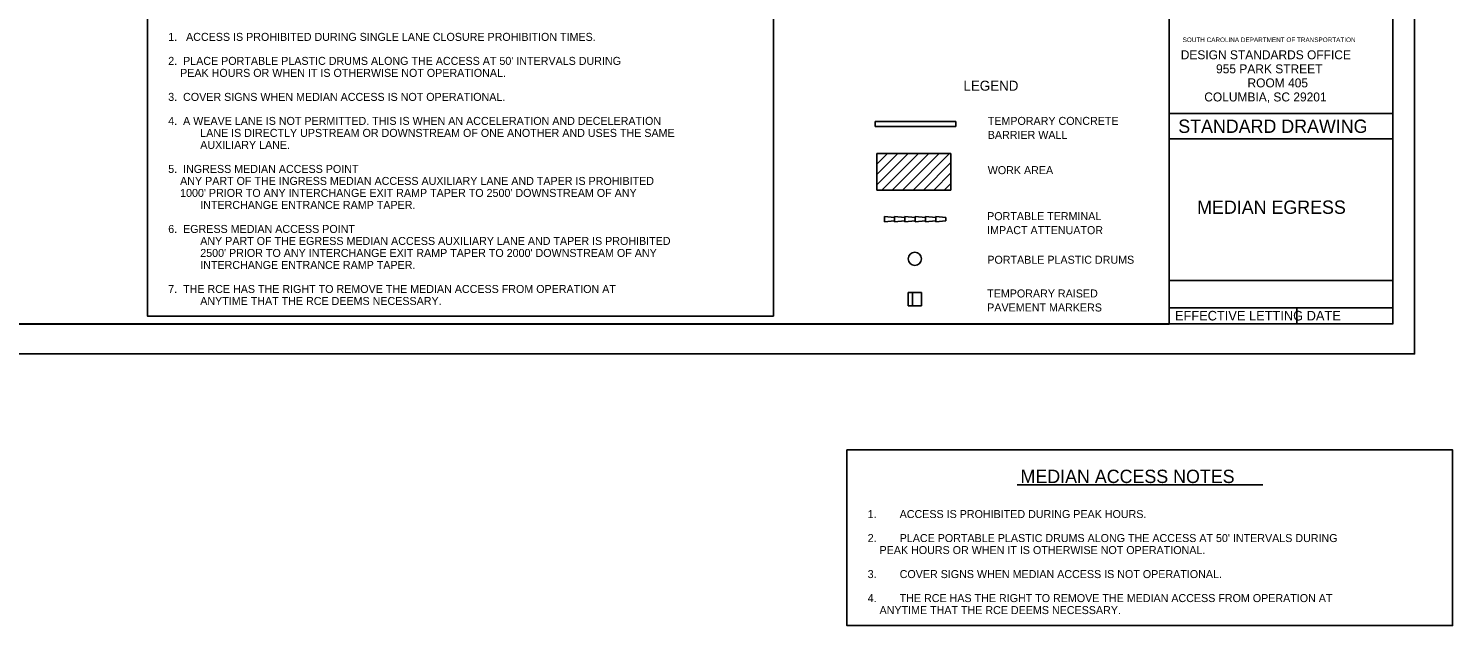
# Model space of a CAD drawing. Extents: x -2433 to -1135, y -5611 to -4633.
# Drawn here: x -1989 to -1135, y -5611 to -5253 of the extents above; entities that cross this region are included whole.
import ezdxf

# ---------------------------------------------------------------- set-up
doc = ezdxf.new("R2010")
doc.units = 0
for name, color, linetype in [('Level 42', 7, 'Continuous'), ('Level 45', 7, 'Continuous'), ('Level 47', 7, 'Continuous'), ('Level 48', 7, 'Continuous'), ('Level 50', 7, 'Continuous'), ('TR_WZ_TC_Edge Lines', 7, 'Continuous'), ('TR_WZ_TC_Text and Notes', 7, 'Continuous')]:
    doc.layers.add(name, color=color, linetype=linetype)

msp = doc.modelspace()

# ---------------------------------------------------------------- linework, layer by layer
at = {"layer": 'Level 42'}
for p, q in [((-1304.73, -5430.02), (-1304.73, -4648.85)), ((-1170.57, -5430.02), (-1170.57, -4648.81)), ((-1304.73, -5303.75), (-1170.64, -5303.75)), ((-1304.73, -5318.83), (-1170.64, -5318.83)), ((-1304.73, -5403.82), (-1170.64, -5403.82)), ((-1304.73, -5420.2), (-1170.72, -5420.2)), ((-1228.17, -5420.2), (-1228.17, -5429.79)), ((-1170.64, -5429.98), (-2364.77, -5429.98))]:
    msp.add_line(p, q, dxfattribs=at)
msp.add_lwpolyline([(-2364.77, -4648.78), (-1304.73, -4648.78), (-1304.73, -5430.02), (-2364.77, -5430.02)], close=True, dxfattribs=at)
at = {"layer": 'Level 45'}
for p, q in [((-1461.35, -5419.02), (-1461.35, -5411.1)), ((-1461.35, -5411.1), (-1458.71, -5411.1)), ((-1453.43, -5411.1), (-1458.71, -5411.1)), ((-1458.71, -5411.1), (-1458.71, -5419.02)), ((-1453.43, -5419.02), (-1453.43, -5411.1)), ((-1461.35, -5419.02), (-1458.71, -5419.02)), ((-1458.71, -5419.02), (-1453.43, -5419.02))]:
    msp.add_line(p, q, dxfattribs=at)
at = {"layer": 'Level 47'}
for p, q in [((-1480.11, -5349.74), (-1480.11, -5327.82)), ((-1480.11, -5346.49), (-1461.44, -5327.82)), ((-1480.11, -5340.26), (-1467.66, -5327.82)), ((-1480.11, -5334.04), (-1473.88, -5327.82)), ((-1480.11, -5327.82), (-1435.7, -5327.82)), ((-1477.14, -5349.74), (-1455.22, -5327.82)), ((-1470.92, -5349.74), (-1448.99, -5327.82)), ((-1464.7, -5349.74), (-1442.77, -5327.82)), ((-1458.48, -5349.74), (-1436.55, -5327.82)), ((-1435.7, -5349.74), (-1435.7, -5327.82)), ((-1452.25, -5349.74), (-1435.7, -5333.19)), ((-1446.03, -5349.74), (-1435.7, -5339.41)), ((-1439.81, -5349.74), (-1435.7, -5345.63)), ((-1480.11, -5349.74), (-1435.7, -5349.74))]:
    msp.add_line(p, q, dxfattribs=at)
at = {"layer": 'Level 48'}
for p, q in [((-1432.83, -5308.63), (-1481.16, -5308.63)), ((-1481.16, -5308.63), (-1481.16, -5311.56)), ((-1481.16, -5311.56), (-1432.83, -5311.56))]:
    msp.add_line(p, q, dxfattribs=at)
msp.add_lwpolyline([(-1432.83, -5311.56), (-1432.83, -5308.63)], dxfattribs=at)
at = {"layer": 'Level 50'}
for p, q in [((-1469.49, -5366.06), (-1475.64, -5365.54)), ((-1475.64, -5365.54), (-1475.64, -5368.7)), ((-1475.64, -5368.7), (-1469.49, -5368.18)), ((-1463.34, -5366.06), (-1469.49, -5365.53)), ((-1469.49, -5365.53), (-1469.49, -5368.7)), ((-1469.49, -5368.18), (-1469.49, -5366.06)), ((-1469.49, -5368.7), (-1463.34, -5368.18)), ((-1457.18, -5366.06), (-1463.34, -5365.54)), ((-1463.34, -5365.54), (-1463.34, -5368.7)), ((-1463.34, -5368.18), (-1463.34, -5366.06)), ((-1463.34, -5368.7), (-1457.18, -5368.18)), ((-1451.03, -5366.06), (-1457.18, -5365.54)), ((-1457.18, -5365.54), (-1457.18, -5368.7)), ((-1457.18, -5368.18), (-1457.18, -5366.06)), ((-1457.18, -5368.7), (-1451.03, -5368.18)), ((-1444.87, -5366.06), (-1451.03, -5365.54)), ((-1451.03, -5365.54), (-1451.03, -5368.7)), ((-1451.03, -5368.18), (-1451.03, -5366.06)), ((-1451.03, -5367.12), (-1451.03, -5367.12)), ((-1451.03, -5368.7), (-1444.88, -5368.18)), ((-1444.88, -5368.18), (-1444.87, -5366.06)), ((-1438.72, -5366.06), (-1444.87, -5365.54)), ((-1444.87, -5365.54), (-1444.87, -5368.7)), ((-1444.87, -5368.7), (-1438.72, -5368.18)), ((-1438.72, -5368.18), (-1438.72, -5366.06))]:
    msp.add_line(p, q, dxfattribs=at)
msp.add_lwpolyline([(-2432.94, -4632.82), (-1157.59, -4632.82), (-1157.59, -5447.91), (-2432.94, -5447.91)], close=True, dxfattribs=at)
msp.add_circle((-1457.35, -5390.92), 3.96, dxfattribs=at)
at = {"layer": 'TR_WZ_TC_Edge Lines'}
for points in [[(-1917.72, -5229.67), (-1542.19, -5229.67), (-1542.19, -5425.27), (-1917.72, -5425.27)], [(-1498.14, -5505.54), (-1134.84, -5505.54), (-1134.84, -5610.83), (-1498.14, -5610.83)]]:
    msp.add_lwpolyline(points, close=True, dxfattribs=at)
at = {"layer": 'TR_WZ_TC_Text and Notes'}
msp.add_line((-1395.94, -5526.38), (-1248.62, -5526.38), dxfattribs=at)

# ---------------------------------------------------------------- texts
at = {"layer": 'Level 42'}
for s, height, p in [('SOUTH CAROLINA DEPARTMENT OF TRANSPORTATION', 2.76, (-1296.74, -5260.91)), ('DESIGN STANDARDS OFFICE', 5.3667, (-1297.86, -5271.2)), ('955 PARK STREET', 5.3667, (-1276.68, -5279.64)), ('LEGEND', 6, (-1428.24, -5290.07)), ('ROOM 405', 5.367, (-1257.82, -5288.07)), ('COLUMBIA, SC 29201', 5.3667, (-1283.76, -5296.5)), ('TEMPORARY CONCRETE', 4.8, (-1413.64, -5310.57)), ('STANDARD DRAWING', 8, (-1299.36, -5315.37)), ('BARRIER WALL', 4.8, (-1413.64, -5318.97)), ('WORK AREA', 4.8, (-1413.65, -5340.11)), ('MEDIAN EGRESS', 8, (-1288.02, -5363.92)), ('PORTABLE TERMINAL', 4.8, (-1414.02, -5367.7)), ('IMPACT ATTENUATOR', 4.8, (-1414.02, -5376.1)), ('PORTABLE PLASTIC DRUMS', 4.8, (-1413.9, -5393.85)), ('TEMPORARY RAISED', 4.8, (-1413.98, -5414.08)), ('PAVEMENT MARKERS', 4.8, (-1413.98, -5422.48)), ('EFFECTIVE LETTING DATE', 5.75, (-1301.36, -5427.87))]:
    msp.add_text(s, height=height, dxfattribs=at).set_placement(p)
at = {"layer": 'TR_WZ_TC_Text and Notes'}
for s, height, p in [('1.   ACCESS IS PROHIBITED DURING SINGLE LANE CLOSURE PROHIBITION TIMES.', 4.8, (-1905.26, -5260.18)), ("2.  PLACE PORTABLE PLASTIC DRUMS ALONG THE ACCESS AT 50' INTERVALS DURING", 4.8, (-1905.26, -5274.58)), ('    PEAK HOURS OR WHEN IT IS OTHERWISE NOT OPERATIONAL.', 4.8, (-1905.26, -5281.78)), ('3.  COVER SIGNS WHEN MEDIAN ACCESS IS NOT OPERATIONAL.', 4.8, (-1905.26, -5296.18)), ('4.  A WEAVE LANE IS NOT PERMITTED. THIS IS WHEN AN ACCELERATION AND DECELERATION ', 4.8, (-1905.26, -5310.58)), ('LANE IS DIRECTLY UPSTREAM OR DOWNSTREAM OF ONE ANOTHER AND USES THE SAME ', 4.8, (-1886.06, -5317.78)), ('AUXILIARY LANE.', 4.8, (-1886.06, -5324.98)), ('5.  INGRESS MEDIAN ACCESS POINT   ', 4.8, (-1905.26, -5339.38)), ('    ANY PART OF THE INGRESS MEDIAN ACCESS AUXILIARY LANE AND TAPER IS PROHIBITED ', 4.8, (-1905.26, -5346.58)), ("    1000' PRIOR TO ANY INTERCHANGE EXIT RAMP TAPER TO 2500' DOWNSTREAM OF ANY ", 4.8, (-1905.26, -5353.78)), ('INTERCHANGE ENTRANCE RAMP TAPER.', 4.8, (-1886.06, -5360.98)), ('6.  EGRESS MEDIAN ACCESS POINT', 4.8, (-1905.26, -5375.38)), ('ANY PART OF THE EGRESS MEDIAN ACCESS AUXILIARY LANE AND TAPER IS PROHIBITED ', 4.8, (-1886.06, -5382.58)), ("2500' PRIOR TO ANY INTERCHANGE EXIT RAMP TAPER TO 2000' DOWNSTREAM OF ANY ", 4.8, (-1886.06, -5389.78)), ('INTERCHANGE ENTRANCE RAMP TAPER.', 4.8, (-1886.06, -5396.98)), ('7.  THE RCE HAS THE RIGHT TO REMOVE THE MEDIAN ACCESS FROM OPERATION AT ', 4.8, (-1905.26, -5411.38)), ('ANYTIME THAT THE RCE DEEMS NECESSARY.', 4.8, (-1886.06, -5418.58)), ('MEDIAN ACCESS NOTES', 8, (-1393.98, -5525.37)), ('1.', 4.8, (-1485.68, -5546.38)), ('ACCESS IS PROHIBITED DURING PEAK HOURS.', 4.8, (-1466.48, -5546.38)), ('2.', 4.8, (-1485.68, -5560.78)), ("PLACE PORTABLE PLASTIC DRUMS ALONG THE ACCESS AT 50' INTERVALS DURING", 4.8, (-1466.48, -5560.78)), ('    PEAK HOURS OR WHEN IT IS OTHERWISE NOT OPERATIONAL.', 4.8, (-1485.68, -5567.98)), ('3.', 4.8, (-1485.68, -5582.38)), ('COVER SIGNS WHEN MEDIAN ACCESS IS NOT OPERATIONAL.', 4.8, (-1466.48, -5582.38)), ('4.', 4.8, (-1485.68, -5596.78)), ('THE RCE HAS THE RIGHT TO REMOVE THE MEDIAN ACCESS FROM OPERATION AT ', 4.8, (-1466.48, -5596.78)), ('    ANYTIME THAT THE RCE DEEMS NECESSARY.', 4.8, (-1485.68, -5603.98))]:
    msp.add_text(s, height=height, dxfattribs=at).set_placement(p)

doc.saveas('drawing.dxf')
